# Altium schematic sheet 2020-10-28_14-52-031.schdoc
size 284 x 111 mm; SheetNumber: 1; SheetTotal: 1
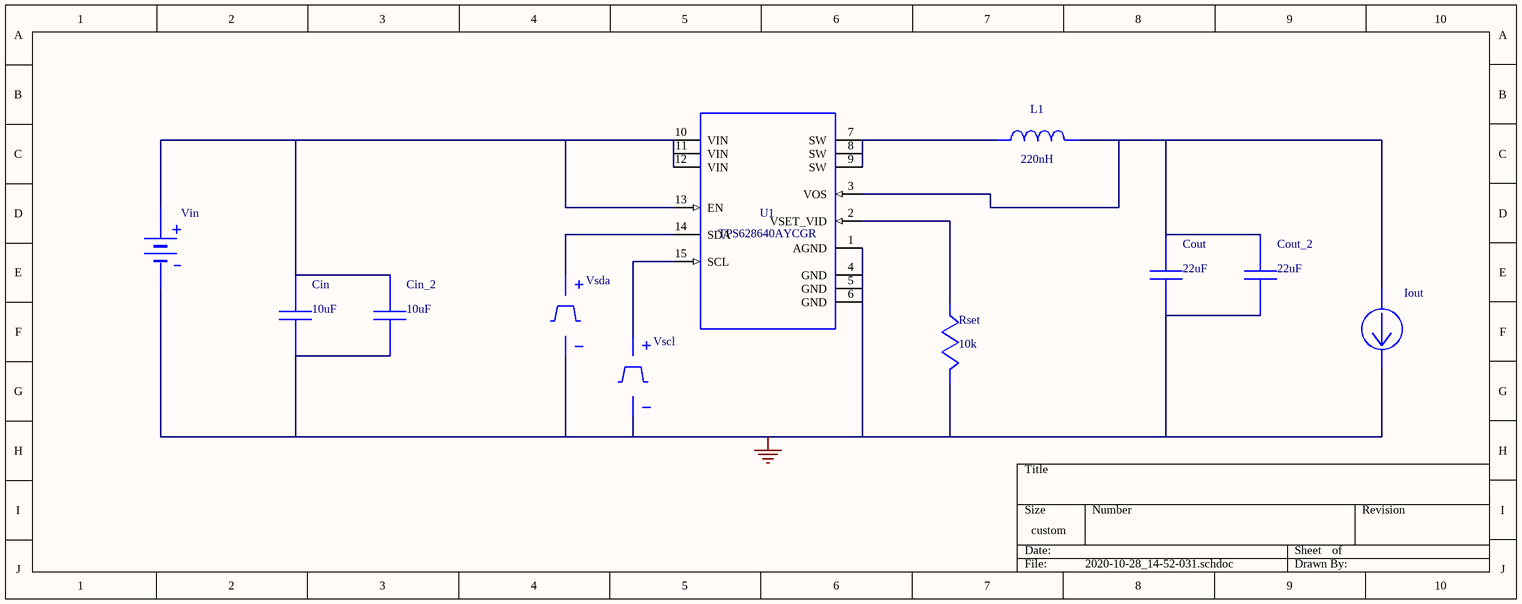
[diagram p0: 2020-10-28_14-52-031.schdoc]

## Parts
Cin  value 10uF  (hidden comment: C0603C106M9PACTU)
Cin_2  value 10uF  (hidden comment: C0603C106M9PACTU)
Cout  value 22uF  (hidden comment: GRM21BR60J226ME39L)
Cout_2  value 22uF  (hidden comment: GRM21BR60J226ME39L)
Iout  WB_CURRENT_LOAD  (value not drawn)
L1  value 220nH  (hidden comment: XAL4020-221MEB)
Rset  value 10k  (hidden comment: CRCW040210K0FKED)
U1  TPS628640AYCGR
Vin  WB_BATTERY  (value not drawn)
Vscl  WB_PRIM_PULSE_VOLTAGE_SOURCE  (value not drawn)
Vsda  WB_PRIM_PULSE_VOLTAGE_SOURCE  (value not drawn)

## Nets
0: Cin.2 Cin_2.2 Cout.2 Cout_2.2 Iout.2(-) Rset.1 U1.1(AGND) U1.4(GND) U1.5(GND) U1.6(GND) Vin.2(-) Vscl.2(-) Vsda.2(-)
NetCin_1: Cin.1 Cin_2.1 U1.10(VIN) U1.11(VIN) U1.12(VIN) U1.13(EN) Vin.1(+)
NetCout_1: Cout.1 Cout_2.1 Iout.1(+) L1.2 U1.3(VOS)
NetL1_1: L1.1 U1.7(SW) U1.8(SW) U1.9(SW)
NetRset_2: Rset.2 U1.2(VSET_VID)
NetU1_14: U1.14(SDA) Vsda.1(+)
NetU1_15: U1.15(SCL) Vscl.1(+)

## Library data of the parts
Cin Cin_2 = C0603C106M9PACTU: Manufacturer Name: Kemet
Cout Cout_2 = GRM21BR60J226ME39L: GRM21BR60J226ME3; Manufacturer Name: MuRata
L1 = XAL4020-221MEB: Manufacturer Name: Coilcraft
Rset = CRCW040210K0FKED: Manufacturer Name: Vishay-Dale
U1 = TPS628640AYCGR: Manufacturer Name: Texas Instruments
Vscl Vsda = WB_PRIM_PULSE_VOLTAGE_SOURCE: WB_PRIM_PULSE_VO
